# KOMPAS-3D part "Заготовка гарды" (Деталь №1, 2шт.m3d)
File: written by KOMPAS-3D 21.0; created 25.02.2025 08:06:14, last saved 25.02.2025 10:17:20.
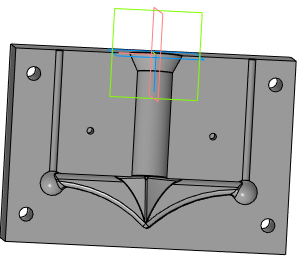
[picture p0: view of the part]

Document properties: Автор: User; Полное имя файла: C:\Users\Цыба.НГ\Работа\Прочее\Колян\Гарда\Форма для литья гарды.m3d

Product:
- Part/product: Заготовка гарды
    Масса: 3.909621

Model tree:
1. Эскиз:1  (with: Элемент вращения:4)
2. Элемент выдавливания:1
     Расстояние 1 = 110
3. Вычесть компоненты:4
4. Эскиз:2  (with: Элемент выдавливания:1)
5. Элемент выдавливания:2
     Расстояние 2 = 160
6. Эскиз:3  (with: Элемент выдавливания:2)
7. Элемент выдавливания:3
8. Эскиз:4  (with: Элемент выдавливания:2)
9. Элемент выдавливания:5
     Расстояние 2 = 10
10. Скругление:1  (with: Вычесть компоненты:4)
     Радиус = 0.5
11. Скругление:2  (with: Вычесть компоненты:4)
     Радиус = 0.5

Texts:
  Точка начала. Х
  Точка начала. Y
  Точка начала. Z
